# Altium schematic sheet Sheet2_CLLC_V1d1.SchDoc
size A3
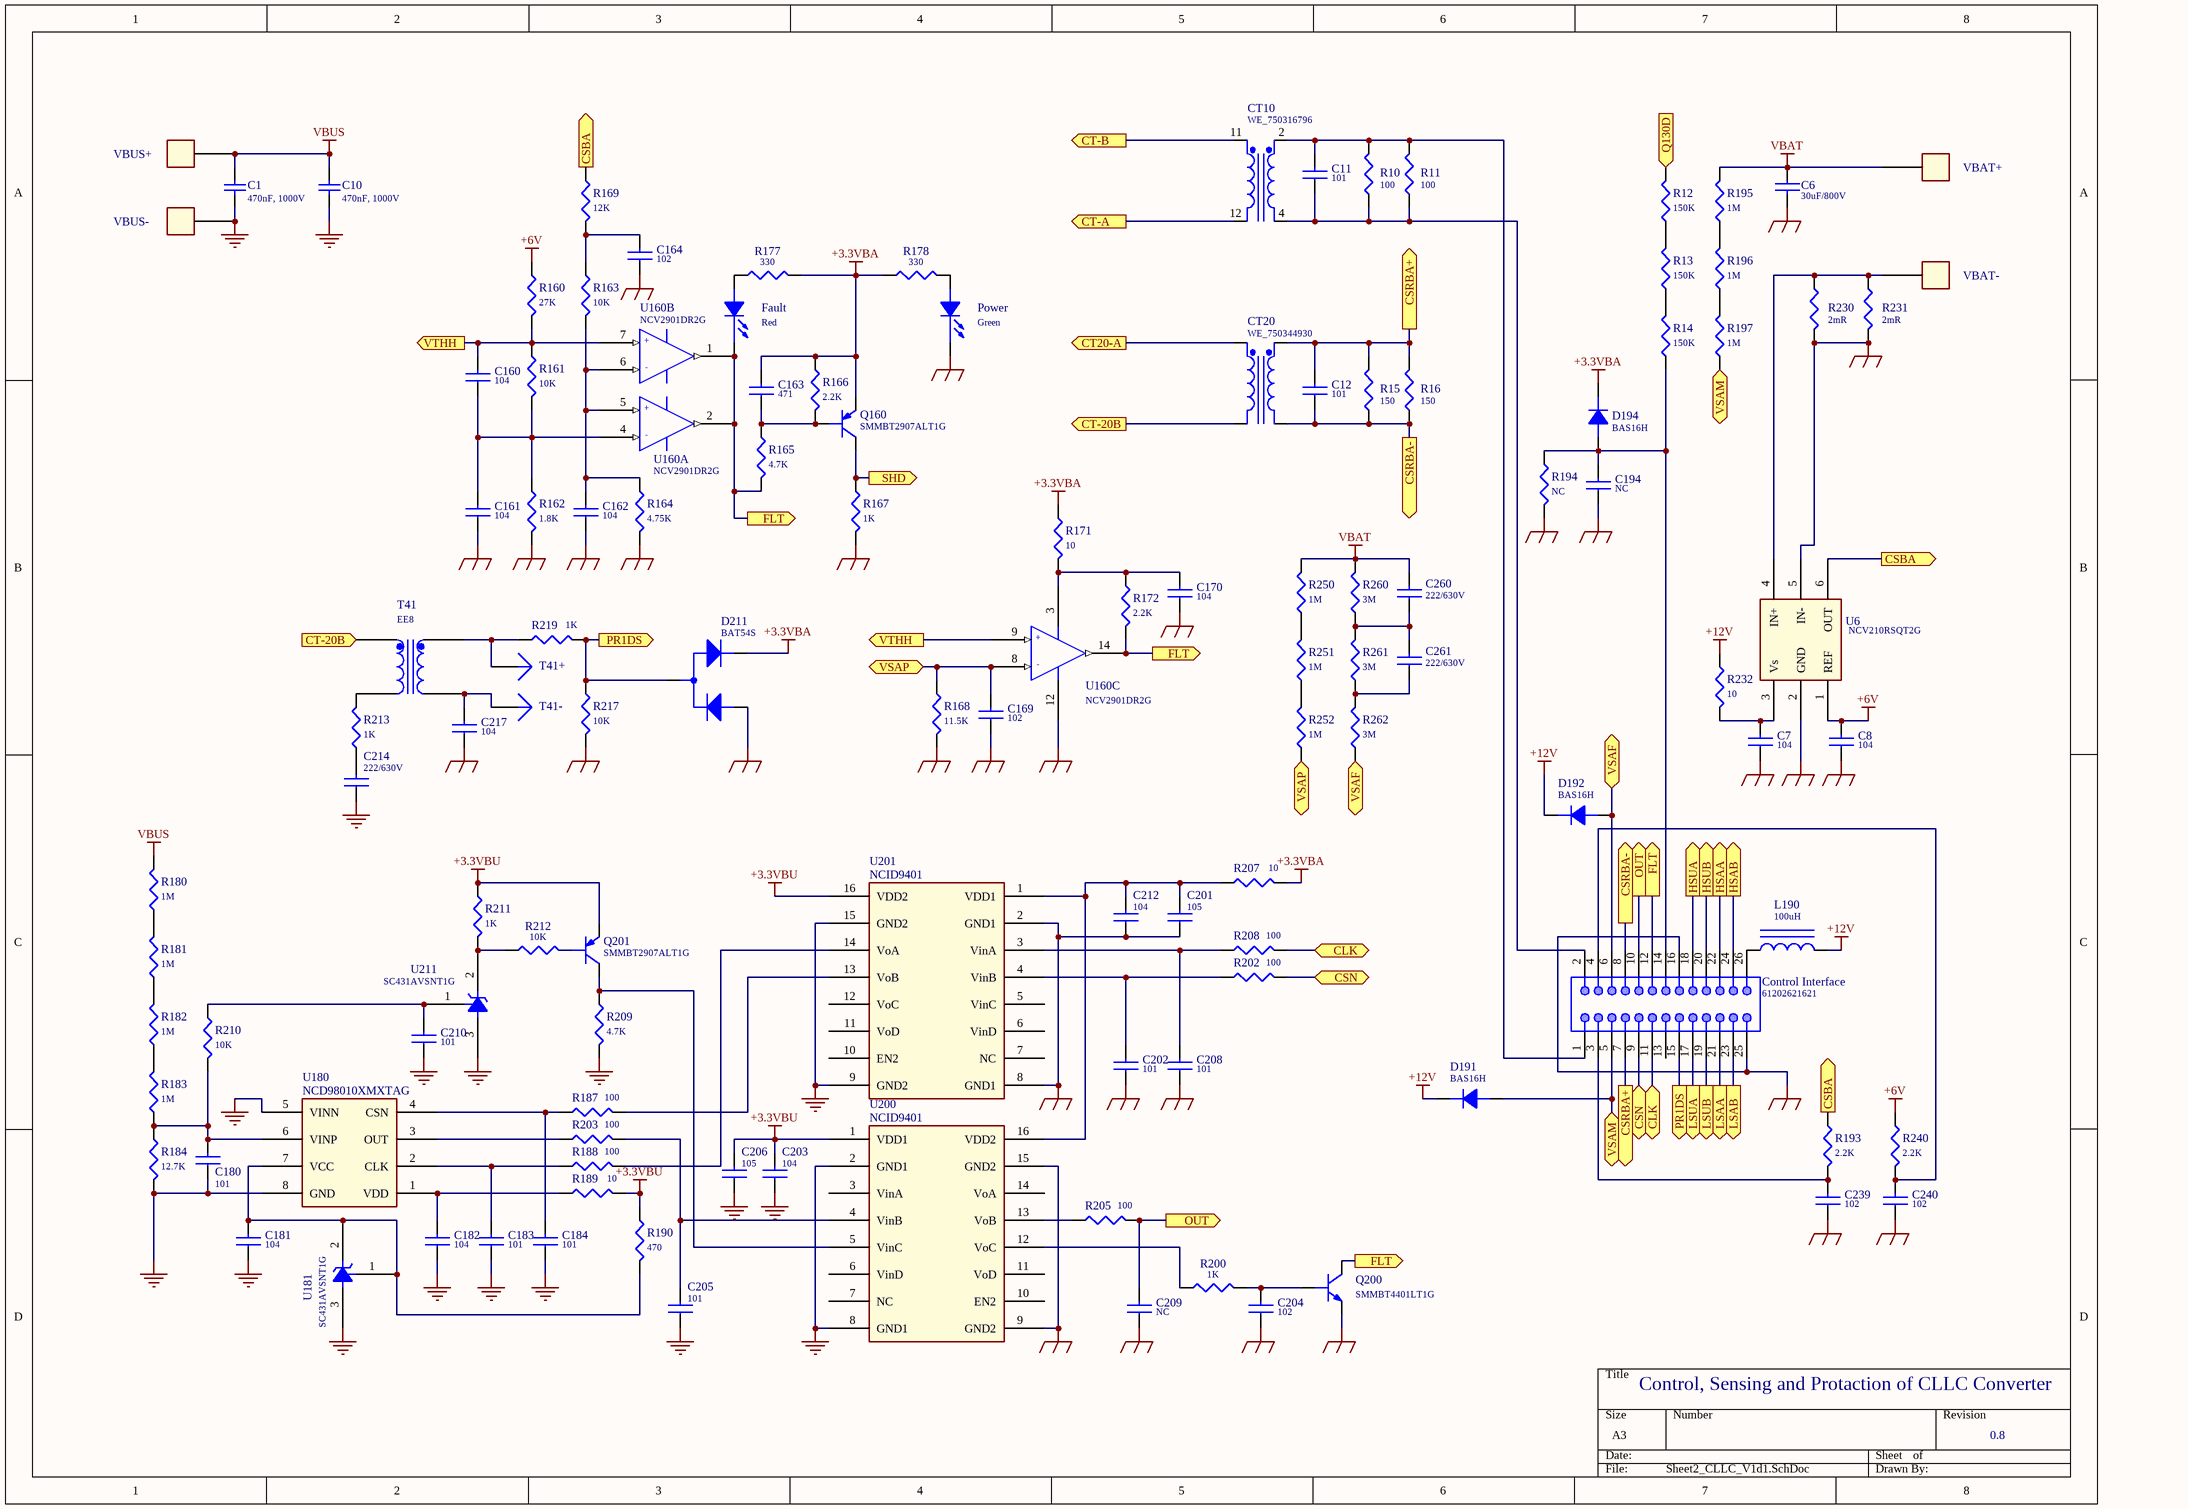
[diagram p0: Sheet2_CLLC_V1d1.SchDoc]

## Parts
C1  470nF, 1000V  [L31_W11_H20_P27.5]
C6  30uF/800V  [CAP-FILM_EZPE_41X30A]
C7  104  [SMT_0805_CM]
C8  104  [SMT_0805_CM]
C10  470nF, 1000V  [L31_W11_H20_P27.5]
C11  101  [SMT_0805_CM]
C12  101  [SMT_0805_CM]
C160  104  [SMT_0805_CM]
C161  104  [SMT_0805_CM]
C162  104  [SMT_0805_CM]
C163  471  [SMT_0805_CM]
C164  102  [SMT_0805_CM]
C169  102  [SMT_0805_CM]
C170  104  [SMT_0805_CM]
C180  101  [SMT_0805_CM]
C181  104  [SMT_0805_CM]
C182  104  [SMT_0805_CM]
C183  101  [SMT_0805_CM]
C184  101  [SMT_0805_CM]
C194  NC  [SMT_0805_CM]
C201  105  [SMT_0805_CM]
C202  101  [SMT_0805_CM]
C203  104  [SMT_0805_CM]
C204  102  [SMT_0805_CM]
C205  101  [SMT_0805_CM]
C206  105  [SMT_0805_CM]
C208  101  [SMT_0805_CM]
C209  NC  [SMT_0805_CM]
C210  101  [SMT_0805_CM]
C212  104  [SMT_0805_CM]
C214  222/630V  [SMT_1206_CM]
C217  104  [SMT_0805_CM]
C239  102  [SMT_0805_CM]
C240  102  [SMT_0805_CM]
C260  222/630V  [SMT_1206_CM]
C261  222/630V  [SMT_1206_CM]
Control_Interface  61202621621  [61202621621]
CT10  WE_750316796  [CT_EE13]
CT20  WE_750344930  [Trans_EE13_6_6_10Pin_V]
D191  BAS16H  [SOD-323M]
D192  BAS16H  [SOD-323M]
D194  BAS16H  [SOD-323M]
D211  BAT54S  [SOT-23-3L]
Fault  Red  [LED 5MM-R]
L190  100uH  [Bead_1210]
Power  Green  [LED 5MM-R]
Q160  SMMBT2907ALT1G  [SOT-23-3L]
Q200  SMMBT4401LT1G  [SOT-23-3L]
Q201  SMMBT2907ALT1G  [SOT-23-3L]
R10  100  [SMT_1206_RM]
R11  100  [SMT_1206_RM]
R12  150K  [SMT_1206_RM]
R13  150K  [SMT_1206_RM]
R14  150K  [SMT_1206_RM]
R15  150  [SMT_1206_RM]
R16  150  [SMT_1206_RM]
R160  27K  [SMT_0805_RM]
R161  10K  [SMT_0805_RM]
R162  1.8K  [SMT_0805_RM]
R163  10K  [SMT_0805_RM]
R164  4.75K  [SMT_0805_RM]
R165  4.7K  [SMT_0805_RM]
R166  2.2K  [SMT_0805_RM]
R167  1K  [SMT_0805_RM]
R168  11.5K  [SMT_0805_RM]
R169  12K  [SMT_0805_RM]
R171  10  [SMT_0805_RM]
R172  2.2K  [SMT_0805_RM]
R177  330  [SMT_0805_RM]
R178  330  [SMT_0805_RM]
R180  1M  [SMT_1206_RM]
R181  1M  [SMT_1206_RM]
R182  1M  [SMT_1206_RM]
R183  1M  [SMT_1206_RM]
R184  12.7K  [SMT_0805_RM]
R187  100  [SMT_0805_RM]
R188  100  [SMT_0805_RM]
R189  10  [SMT_0805_RM]
R190  470  [SMT_0805_RM]
R193  2.2K  [SMT_0805_RM]
R194  NC  [SMT_0805_RM]
R195  1M  [SMT_1206_RM]
R196  1M  [SMT_1206_RM]
R197  1M  [SMT_1206_RM]
R200  1K  [SMT_0805_RM]
R202  100  [SMT_0805_RM]
R203  100  [SMT_0805_RM]
R205  100  [SMT_0805_RM]
R207  10  [SMT_0805_RM]
R208  100  [SMT_0805_RM]
R209  4.7K  [SMT_0805_RM]
R210  10K  [SMT_0805_RM]
R211  1K  [SMT_0805_RM]
R212  10K  [SMT_0805_RM]
R213  1K  [SMT_1206_RM]
R217  10K  [SMT_0805_RM]
R219  1K  [SMT_0805_RM]
R230  2mR  [SMT_2512_R]
R231  2mR  [SMT_2512_R]
R232  10  [SMT_0805_RM]
R240  2.2K  [SMT_0805_RM]
R250  1M  [SMT_1206_RM]
R251  1M  [SMT_1206_RM]
R252  1M  [SMT_1206_RM]
R260  3M  [SMT_1206_RM]
R261  3M  [SMT_1206_RM]
R262  3M  [SMT_1206_RM]
T41  EE8  [EE8]
T41+  (no value)  [PIN1]
T41-  (no value)  [PIN1]
U6  NCV210RSQT2G  [SC70-6]
U160  NCV2901DR2G  [SOP14]  (parts A,B,C of 4)
U180  NCD98010XMXTAG  [SSOP8]
U181  SC431AVSNT1G  [SOT-23-3L]
U200  NCID9401
U201  NCID9401
U211  SC431AVSNT1G  [SOT-23-3L]
VBAT+  (no value)  [TermL]
VBAT-  (no value)  [TermL]
VBUS+  (no value)  [TermL]
VBUS-  (no value)  [TermL]

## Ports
CLK, CSBA (out), CSN, CSRBA+ (out), CSRBA- (out), CT20-A (out), CT-20B (out), CT-A (out), CT-B (out), FLT (out), HSAA (out), HSAB (out), HSUA (out), HSUB (out), LSAA (out), LSAB (out), LSUA (out), LSUB (out), OUT (out), PR1DS (out), Q130D (out), SHD (out), VSAF, VSAM, VSAP, VTHH (out)

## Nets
+3.3VBA: C163.2 D194.2(K) D211.2 Q160.2(E) R166.1 R171.1 R177.2 R178.1 R207.2
+3.3VBU: C203.2 C206.2 Q201.2(E) R189.2 R190.1 R211.1 U200.1(VDD1) U201.16(VDD2)
+6V: C8.2 R160.1 R240.1 U6.1(REF)
+12V: D191.2(K) D192.2(K) L190.2 R232.1
GND: C6.2 C7.1 C8.1 C161.1 C162.1 C164.1 C169.1 C170.1 C194.1 C201.1 C202.1 C204.1 C208.1 C209.1 C212.1 C217.1 C239.1 C240.1 Control_Interface.16 Control_Interface.25 D211.1 Power.2(CATHODE) Q200.2(E) R162.2 R164.2 R167.2 R168.2 R194.2 R217.2 R230.2 R231.2 U6.2(GND) U6.5(IN-) U160.12(GND) U200.9(GND2) U200.15(GND2) U201.2(GND1) U201.8(GND1)
PGND: C1.1 C10.1 C180.1 C181.1 C182.1 C183.1 C184.1 C203.1 C205.1 C206.1 C210.1 C214.1 R184.2 R209.2 U180.5(VINN) U180.8(GND) U181.3(A) U200.2(GND1) U200.8(GND1) U201.9(GND2) U201.15(GND2) U211.3(A) VBUS-.1
VBAT: C6.1 C260.2 R195.2 R250.2 R260.2 VBAT+.1
VBUS: C1.2 C10.2 R180.2 VBUS+.1
CLK: Control_Interface.11 R208.2 ; port CLK
CSBA: R169.1 R193.1 U6.6(OUT) ; port CSBA
CSN: Control_Interface.9 R202.2 ; port CSN
CSRBA+: C12.2 Control_Interface.7 CT20.1(Sec+) R15.2 R16.2 ; port CSRBA+
CSRBA-: C12.1 Control_Interface.8 CT20.2(Sec-) R15.1 R16.1 ; port CSRBA-
CT20-A: CT20.11(Pri+) ; port CT20-A
CT-20B: CT20.12(Pri-) T41.2(S) ; port CT-20B
CT-A: CT10.12(Pri-) ; port CT-A
CT-B: CT10.11(Pri+) ; port CT-B
FLT: Control_Interface.12 Fault.2(CATHODE) Q200.3(C) R165.2 R172.2 U160.1(OUT) U160.2(OUT) U160.14(OUT) ; port FLT
HSAA: Control_Interface.22 ; port HSAA
HSAB: Control_Interface.24 ; port HSAB
HSUA: Control_Interface.18 ; port HSUA
HSUB: Control_Interface.20 ; port HSUB
LSAA: Control_Interface.21 ; port LSAA
LSAB: Control_Interface.23 ; port LSAB
LSUA: Control_Interface.17 ; port LSUA
LSUB: Control_Interface.19 ; port LSUB
OUT: C209.2 Control_Interface.10 R205.2 ; port OUT
PR1DS: Control_Interface.15 D211.3 R217.1 R219.2 ; port PR1DS
Q130D: R12.2 ; port Q130D
SHD: Q160.3(C) R167.1 ; port SHD
VSAF: Control_Interface.6 D192.1(A) R262.1 ; port VSAF
VSAM: Control_Interface.5 D191.1(A) R197.1 ; port VSAM
VSAP: C169.2 R168.1 R252.1 U160.8(-IN) ; port VSAP
VTHH: C160.2 R160.2 R161.1 U160.7(+IN) U160.9(+IN) ; port VTHH
NetC7_2: C7.2 R232.2 U6.3(Vs)
NetC11_1: C11.1 Control_Interface.2 CT10.4(Sec-) R10.1 R11.1
NetC11_2: C11.2 Control_Interface.1 CT10.2(Sec+) R10.2 R11.2
NetC160_1: C160.1 C161.2 R161.2 R162.1 U160.4(-IN)
NetC162_2: C162.2 R163.2 R164.1 U160.5(+IN) U160.6(-IN)
NetC163_1: C163.1 Q160.1(B) R165.1 R166.2
NetC164_2: C164.2 R163.1 R169.2
NetC170_2: C170.2 R171.2 R172.1 U160.3(VCC)
NetC180_2: C180.2 R183.1 R184.1 R210.2 U180.6(VINP)
NetC181_2: C181.2 R190.2 U180.7(VCC) U181.1(REF) U181.2(K)
NetC182_2: C182.2 R189.1 U180.1(VDD)
NetC183_2: C183.2 R188.1 U180.2(CLK)
NetC184_2: C184.2 R187.1 U180.4(CSN)
NetC194_2: C194.2 Control_Interface.14 D194.1(A) R14.1 R194.1
NetC201_2: C201.2 C212.2 R207.1 U200.16(VDD2) U201.1(VDD1)
NetC202_2: C202.2 R202.1 U201.4(VinB)
NetC204_2: C204.2 Q200.1(B) R200.2
NetC205_2: C205.2 R203.2 U200.4(VinB)
NetC208_2: C208.2 R208.1 U201.3(VinA)
NetC210_2: C210.2 R210.1 U211.1(REF)
NetC214_2: C214.2 R213.1
NetC217_2: C217.2 T41.4 T41-.1
NetC239_2: C239.2 Control_Interface.3 R193.2
NetC240_2: C240.2 Control_Interface.4 R240.2
NetC260_1: C260.1 C261.2 R260.1 R261.2
NetC261_1: C261.1 R261.1 R262.2
NetControl_Interface_26: Control_Interface.26 L190.1
NetFault_1: Fault.1(ANODE) R177.1
NetPower_1: Power.1(ANODE) R178.2
NetQ201_1: Q201.1(B) R212.2
NetQ201_3: Q201.3(C) R209.1 U200.5(VinC)
NetR12_1: R12.1 R13.2
NetR13_1: R13.1 R14.2
NetR180_1: R180.1 R181.2
NetR181_1: R181.1 R182.2
NetR182_1: R182.1 R183.2
NetR187_2: R187.2 U201.13(VoB)
NetR188_2: R188.2 U201.14(VoA)
NetR195_1: R195.1 R196.2
NetR196_1: R196.1 R197.2
NetR200_1: R200.1 U200.12(VoC)
NetR203_1: R203.1 U180.3(OUT)
NetR205_1: R205.1 U200.13(VoB)
NetR211_2: R211.2 R212.1 U211.2(K)
NetR213_2: R213.2 T41.1(F)
NetR219_1: R219.1 T41.3 T41+.1
NetR230_1: R230.1 R231.1 U6.4(IN+) VBAT-.1
NetR250_1: R250.1 R251.2
NetR251_1: R251.1 R252.2

Not connected (* = marked no-connect by the designer): Control_Interface 13; U200 3(VinA) 6(VinD) 7(NC) 10(EN2) 11(VoD) 14(VoA); U201 5(VinC) 6(VinD) 7(NC) 10(EN2) 11(VoD) 12(VoC)

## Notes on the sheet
- Control, Sensing and Protaction of CLLC Converter
- 0.8

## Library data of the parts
C1 C10 = 890493427007CS: WCAP-FTBE THT Film Capacitors, 470nF, 1000VDC; Insulation Resistance: 3000Ohm x F; Dissipation Factor@100kHz: 4.3%; Dissipation Factor@1kHz: 1%; Dissipation Factor@10kHz: 1.5%; Pitch: 27.5mm; Rate of Voltage Rise: 22V/us; Technical Reference: MPSP275474KA00DCPP35004
C6 = CAP NP: EZPE80306MTA
C7 C8 C11 C12 C160-C164 C169 C170 C180-C184 C194 C201-C206 C208-C210 C212 C217 C239 C240 = CAP_0805
C214 C260 C261 = CAP NP
Control_Interface = 61202621621: Male Box Header WR-BHD, THT, Vertical, pitch 2.54 mm, 26 pins; Pitch: 2.54 mm; Working Voltage: 250 VAC; Withstanding Voltage: 500 VAC; Contact Resistance: 20 mOhm; Pin Number: 26
CT10 CT20 = Trans Cupl: Transformer (Coupled Inductor Model)
D191 D192 D194 = DIODE
D211 = BAT54S/SOT
Fault Power = LED
L190 = INDUCTOR IRON
Q160 Q201 = Q_PNP_SOT-23-3L
Q200 = NPN BCE
R10-R16 R160-R169 R171 R172 R180-R184 R190 R193-R197 R209-R211 R213 R217 R230-R232 R240 R250-R252 R260-R262 = R
R177 R178 R187-R189 R200 R202 R203 R205 R207 R208 R212 R219 = R_0805
T41 = TRAN_HM31
T41+ T41- = Plug
U6 = NCV210
U160 = LM339
U180 = NCD98010
U181 U211 = TL431
VBAT+ VBAT- VBUS+ VBUS- = P_1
